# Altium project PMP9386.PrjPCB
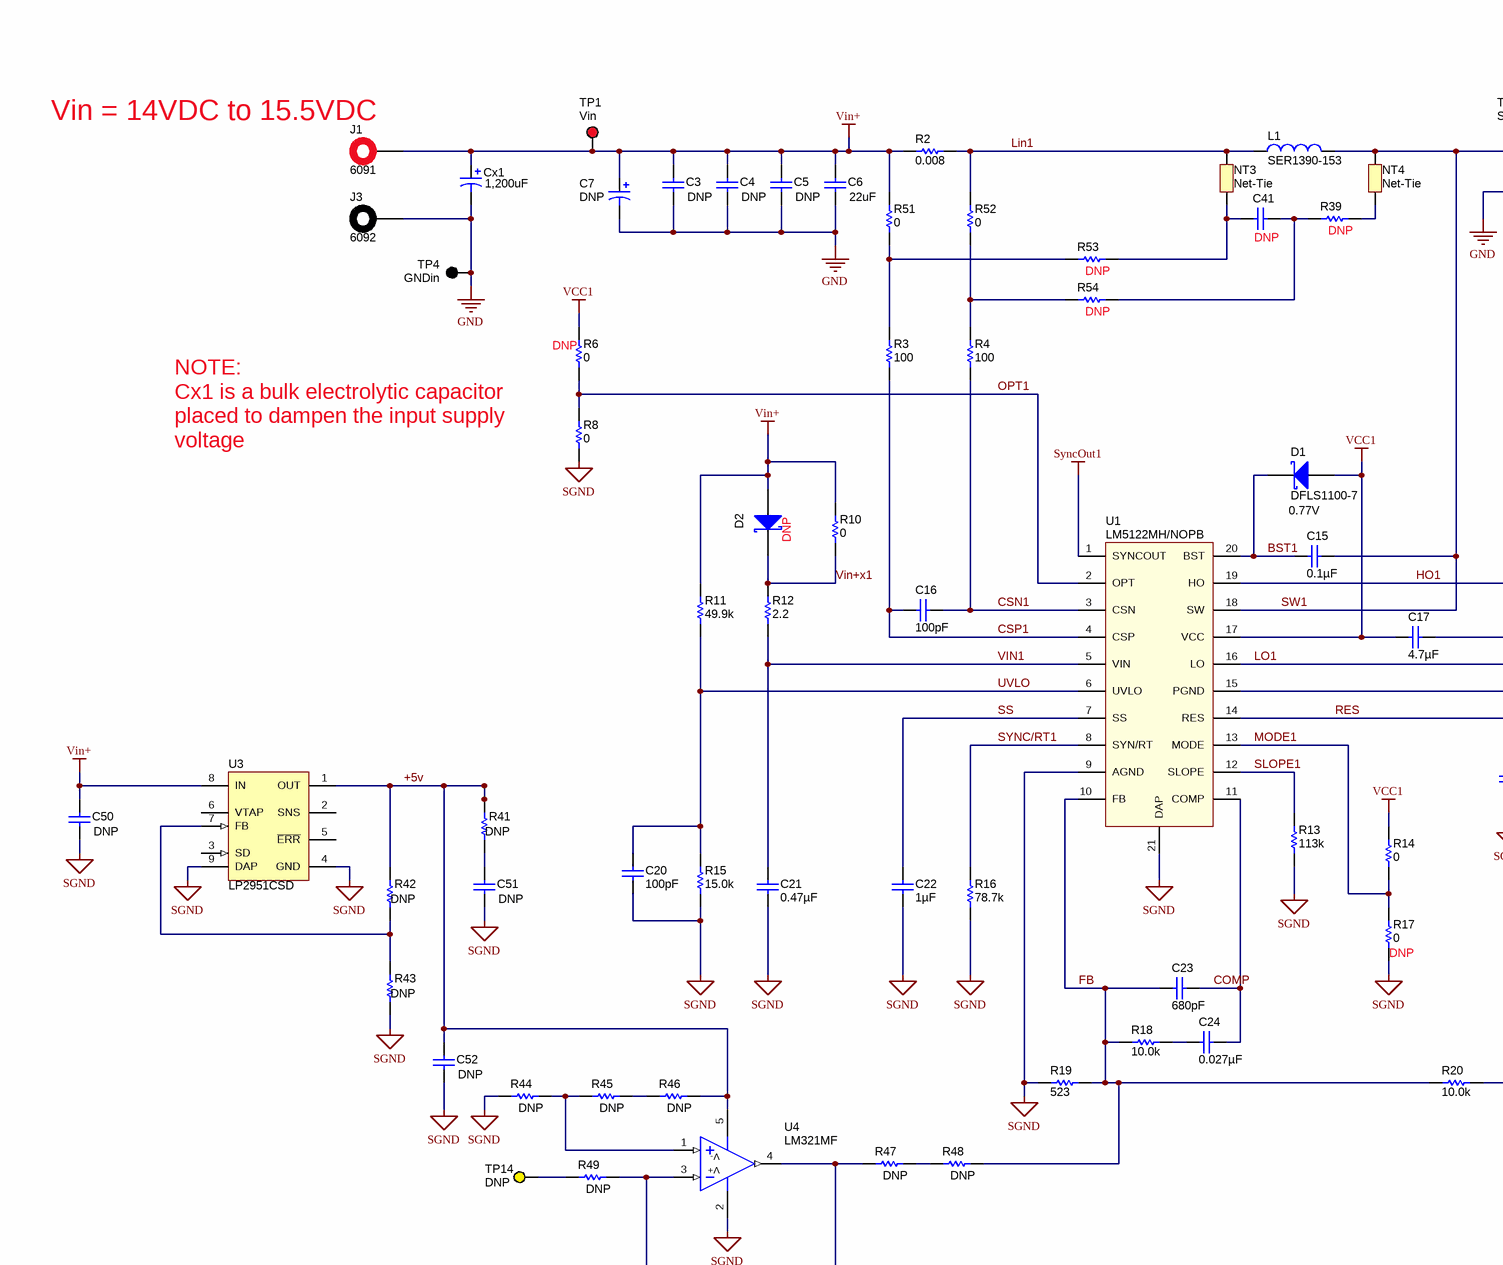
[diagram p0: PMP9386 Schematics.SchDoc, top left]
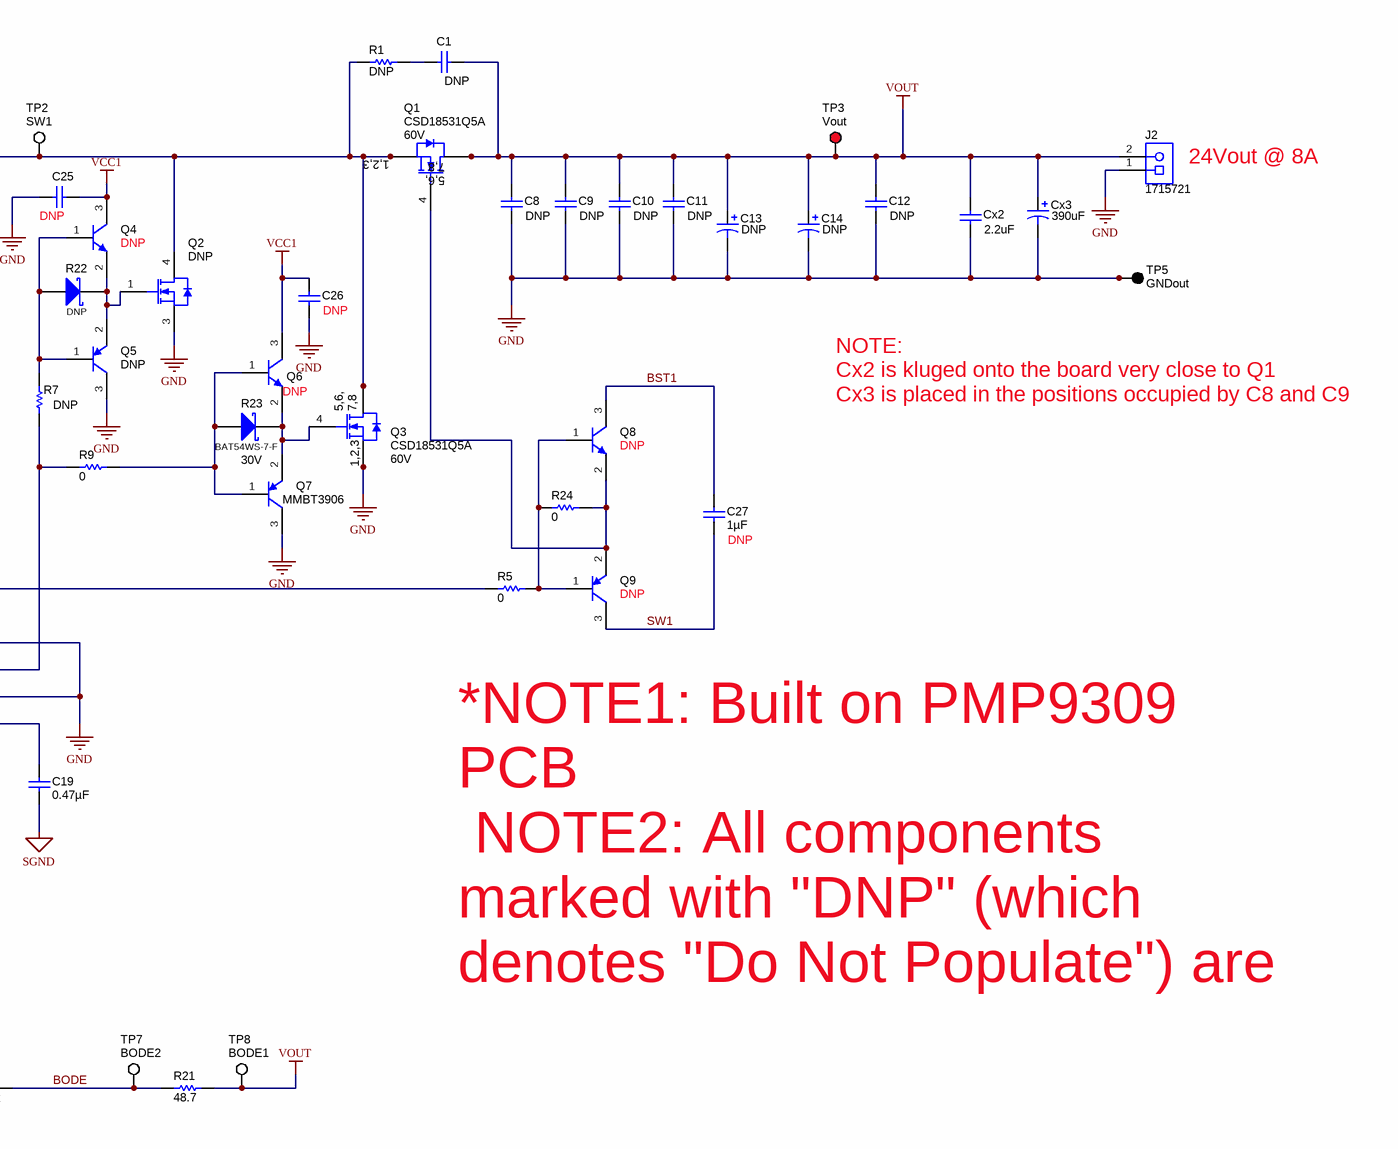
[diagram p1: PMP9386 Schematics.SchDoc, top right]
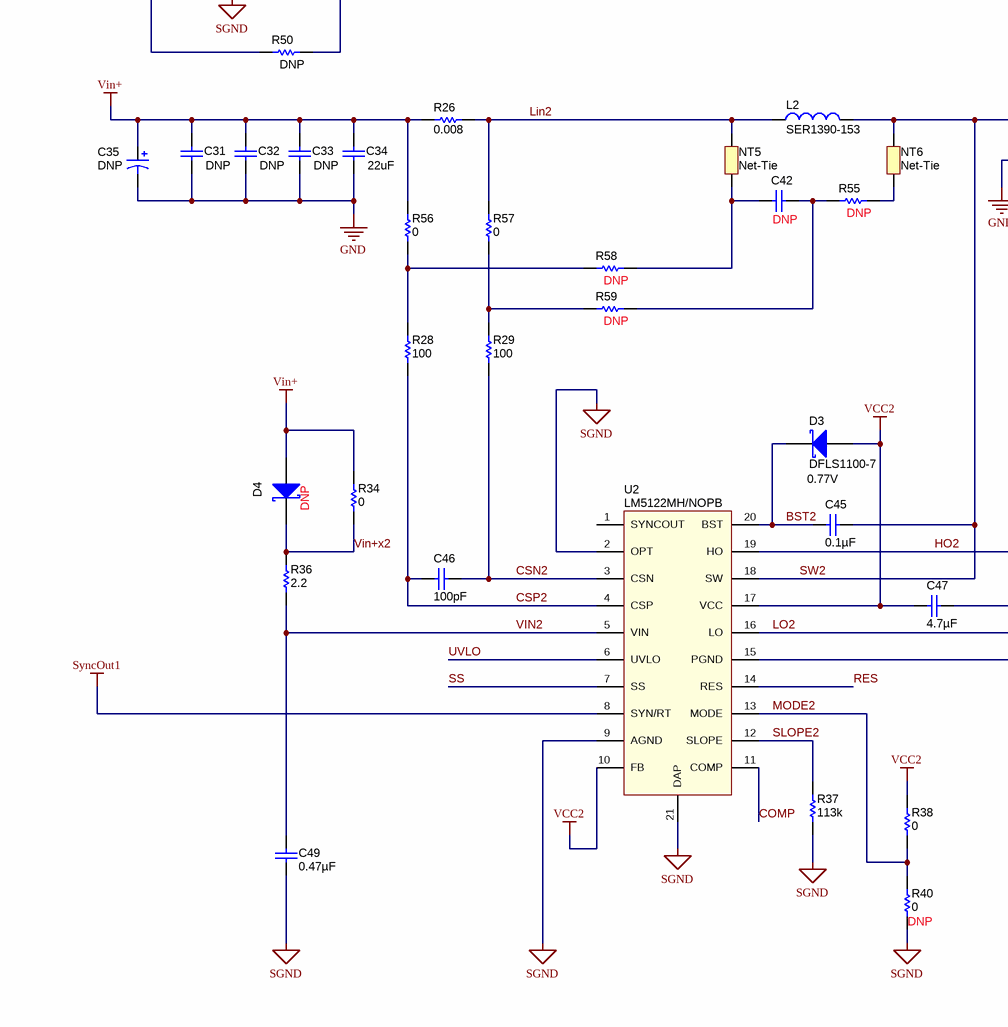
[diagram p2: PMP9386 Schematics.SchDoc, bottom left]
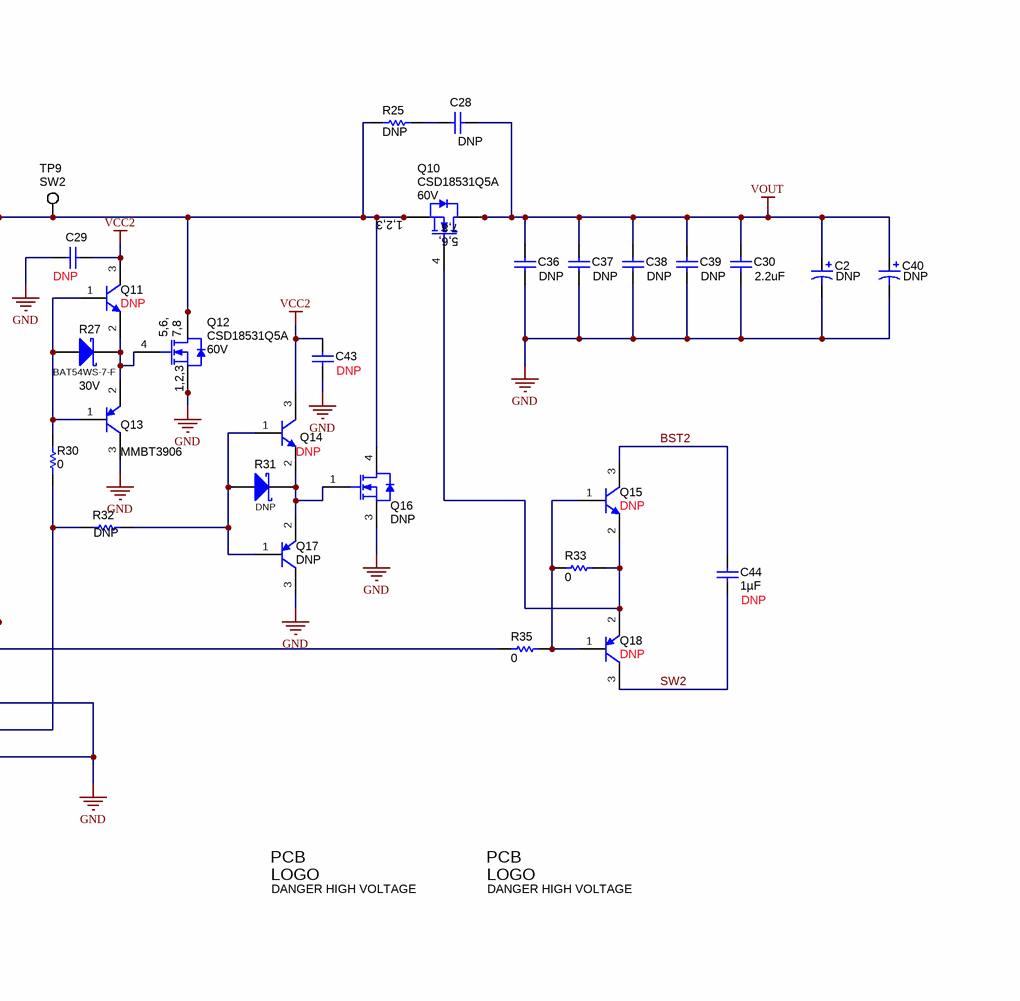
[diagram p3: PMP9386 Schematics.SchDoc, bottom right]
CopyrightYear: 2014; PCB_Layout: David Baba; PCB_Rev: Rev3C; PRJ_Customer: Public Release; PRJ_Engineer: David Baba; PRJ_Number: PMP9386; PRJ_Title: LM5122 Sync Boost; SCH_Rev: E1; TechSupport: http://www.ti.com/support; TID: PMP9386
2 sheets, 176 parts. Net scope: global (net labels, ports and power ports of the same name join across sheets).
Board file: PMP9309.PcbDoc
Sheets:
  PMP9386 Schematics.SchDoc
  PMP9386_Hardware_ANSI-B.SchDoc

## Sheet PMP9386 Schematics.SchDoc
size 558 x 431 mm; Date: Not shown in title block; ApprovedBy: Not shown in title block; CheckedBy: Not shown in title block; Author: Not shown in title block; CompanyName: Not shown in title block; Engineer: Not shown in title block; Organization: Not shown in title block; Address1: Not shown in title block; Address2: Not shown in title block; Address3: Not shown in title block; Address4: Not shown in title block; DocumentNumber: 1; Revision: Use project parameter SCH_Rev; SheetNumber: 1; SheetTotal: 2; PageSetup: Record=PageOptions¦CenterHorizontal=True¦CenterVertical=True¦PrintScale=0.62¦XCorrection=1.00¦YCorrection=1.00¦PrintKind=0¦BorderSize=5000000¦LeftOffset=0¦BottomOffset=0¦Orientation=2¦PaperLength=1000¦PaperWidth=1000¦Scale=100¦PaperSource=15¦PrintQuality=600¦MediaType=1¦DitherType=10¦PaperKind=11x17¦PrintScaleMode=1

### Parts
C1  DNP  [0805_HV]
C2  DNP  [SM_RADIAL_K16]
C3  DNP  [1210]
C4  DNP  [1210]
C5  DNP  [1210]
C6  22uF  [TBD]
C7  DNP  [TBD]
C8  DNP  [1210]
C9  DNP  [1210]
C10  DNP  [1210]
C11  DNP  [1210]
C12  DNP  [1210]
C13  DNP  [SM_RADIAL_K16]
C14  DNP  [SM_RADIAL_K16]
C15  ValueDisplayed: 0.1µF  [0603_HV]  (hidden comment: GRM188R72A104KA35D)
C16  ValueDisplayed: 100pF  [0603_HV]  (hidden comment: C1608C0G2A101J)
C17  ValueDisplayed: 4.7µF  [0805]  (hidden comment: GRM21BR71C475KA73L)
C19  ValueDisplayed: 0.47µF  [0603]  (hidden comment: GRM188R71E474KA12D)
C20  ValueDisplayed: 100pF  [0603_HV]  (hidden comment: GRM1885C1H101JA01D)
C21  ValueDisplayed: 0.47µF  [0603_HV]  (hidden comment: GRM188R71E474KA12D)
C22  ValueDisplayed: 1µF  [0805_HV]  (hidden comment: GRM219R71E105KA88D)
C23  ValueDisplayed: 680pF  [0603]  (hidden comment: C0603C681K5RACTU)
C24  ValueDisplayed: 0.027µF  [0805_HV]  (hidden comment: C0805C273K5RACTU)
C25  DNP  [0603]
C26  DNP  [0603]
C27  DNP  ValueDisplayed: 1µF  [0603]
C28  DNP  [0805_HV]
C29  DNP  [0603]
C30  2.2uF  [TBD]
C31  DNP  [1210]
C32  DNP  [1210]
C33  DNP  [1210]
C34  22uF  [TBD]
C35  DNP  [TBD]
C36  DNP  [1210]
C37  DNP  [1210]
C38  DNP  [1210]
C39  DNP  [1210]
C40  DNP  [SM_RADIAL_K16]
C41  DNP  [1206]
C42  DNP  [1206]
C43  DNP  [0603]
C44  DNP  ValueDisplayed: 1µF  [0603]
C45  ValueDisplayed: 0.1µF  [0603_HV]  (hidden comment: GRM188R72A104KA35D)
C46  ValueDisplayed: 100pF  [0603_HV]  (hidden comment: C1608C0G2A101J)
C47  ValueDisplayed: 4.7µF  [0805]  (hidden comment: GRM21BR71C475KA73L)
C49  ValueDisplayed: 0.47µF  [0603_HV]  (hidden comment: GRM188R71E474KA12D)
C50  DNP  [0603]
C51  DNP  [0603]
C52  DNP  [0603]
Cx1  1,200uF  [TBD]
Cx2  2.2uF  [TBD]
Cx3  390uF  [TBD]
D1  DFLS1100-7  value 0.77V  [powerDI123]
D2  DNP  [SOD-123F]
D3  DFLS1100-7  value 0.77V  [powerDI123]
D4  DNP  [SOD-123F]
J1  6091  [6091]
J2  1715721  [PhoenixContact_1715721]
J3  6092  [6092]
L1  SER1390-153
L2  SER1390-153
Logo2  DANGER HIGH VOLTAGE  [IEC_HighVoltage_Medium]  (no BOM)
Logo3  DANGER HIGH VOLTAGE  [IEC_HighVoltage_Medium]  (no BOM)
NT3  Net-Tie  [Net-Tie_10milWide_30milLong]  (net tie, no BOM)
NT4  Net-Tie  [Net-Tie_10milWide_30milLong]  (net tie, no BOM)
NT5  Net-Tie  [Net-Tie_10milWide_30milLong]  (net tie, no BOM)
NT6  Net-Tie  [Net-Tie_10milWide_30milLong]  (net tie, no BOM)
Q1  CSD18531Q5A  value 60V  [TRANS_NexFET_Q5A]
Q2  DNP  [DDPAK]
Q3  CSD18531Q5A  value 60V  [TRANS_NexFET_Q5A]
Q4  DNP  [SOT-23]
Q5  DNP  [SOT-23]
Q6  DNP  [SOT-23]
Q7  MMBT3906  [SOT-23]
Q8  DNP  [SOT-23]
Q9  DNP  [SOT-23]
Q10  CSD18531Q5A  value 60V  [TRANS_NexFET_Q5A]
Q11  DNP  [SOT-23]
Q12  CSD18531Q5A  value 60V  [TRANS_NexFET_Q5A]
Q13  MMBT3906  [SOT-23]
Q14  DNP  [SOT-23]
Q15  DNP  [SOT-23]
Q16  DNP  [DDPAK]
Q17  DNP  [SOT-23]
Q18  DNP  [SOT-23]
R1  DNP  [2010]
R2  value 0.008  [2512M]  (hidden comment: PMR100HZPFU8L00)
R3  value 100  [0603_HV]  (hidden comment: CRCW0603100RFKEA)
R4  value 100  [0603_HV]  (hidden comment: CRCW0603100RFKEA)
R5  value 0  [0603_HV]  (hidden comment: ERJ-3GEY0R00V)
R6  DNP  value 0  [0603_HV]
R7  DNP  [0603_HV]
R8  value 0  [0603_HV]  (hidden comment: ERJ-3GEY0R00V)
R9  value 0  [0603_HV]  (hidden comment: ERJ-3GEY0R00V)
R10  value 0  [0603]  (hidden comment: ERJ-3GEY0R00V)
R11  value 49.9k  [0603]  (hidden comment: CRCW060349K9FKEA)
R12  value 2.2  [0805_HV]  (hidden comment: CRCW08052R20JNEA)
R13  value 113k  [0603]  (hidden comment: CRCW0603113KFKEA)
R14  value 0  [0603]  (hidden comment: ERJ-3GEY0R00V)
R15  value 15.0k  [0603]  (hidden comment: CRCW060315K0FKEA)
R16  value 78.7k  [0603]  (hidden comment: CRCW060378K7FKEA)
R17  DNP  value 0  [0603]
R18  value 10.0k  [0603]  (hidden comment: CRCW060310K0FKEA)
R19  value 523  [0603]  (hidden comment: CRCW0603523RFKEA)
R20  value 10.0k  [0603]  (hidden comment: CRCW060310K0FKEA)
R21  value 48.7  [0805_HV]  (hidden comment: CRCW080548R7FKEA)
R22  DNP  [sod-323]
R23  BAT54WS-7-F  value 30V  [sod-323]
R24  value 0  [0603]  (hidden comment: CRCW06030000Z0EA)
R25  DNP  [2010]
R26  value 0.008  [2512M]  (hidden comment: PMR100HZPFU8L00)
R27  BAT54WS-7-F  value 30V  [sod-323]
R28  value 100  [0603_HV]  (hidden comment: CRCW0603100RFKEA)
R29  value 100  [0603_HV]  (hidden comment: CRCW0603100RFKEA)
R30  value 0  [0603_HV]  (hidden comment: ERJ-3GEY0R00V)
R31  DNP  [sod-323]
R32  DNP  [0603_HV]
R33  value 0  [0603]  (hidden comment: CRCW06030000Z0EA)
R34  value 0  [0603]  (hidden comment: ERJ-3GEY0R00V)
R35  value 0  [0603_HV]  (hidden comment: ERJ-3GEY0R00V)
R36  value 2.2  [0805_HV]  (hidden comment: CRCW08052R20JNEA)
R37  value 113k  [0603]  (hidden comment: CRCW0603113KFKEA)
R38  value 0  [0603]  (hidden comment: ERJ-3GEY0R00V)
R39  DNP  [0805_HV]
R40  DNP  value 0  [0603]
R41  DNP  [0603]
R42  DNP  [0603]
R43  DNP  [0603]
R44  DNP  [0603]
R45  DNP  [0603]
R46  DNP  [0603]
R47  DNP  [0603]
R48  DNP  [0603]
R49  DNP  [0603]
R50  DNP  [0603]
R51  value 0  [0603]  (hidden comment: CRCW06030000Z0EA)
R52  value 0  [0603]  (hidden comment: CRCW06030000Z0EA)
R53  DNP  [1206]
R54  DNP  [1206]
R55  DNP  [0805_HV]
R56  value 0  [0603]  (hidden comment: CRCW06030000Z0EA)
R57  value 0  [0603]  (hidden comment: CRCW06030000Z0EA)
R58  DNP  [1206]
R59  DNP  [1206]
TP1  Vin  [Keystone5010]
TP2  SW1  [Keystone5012]
TP3  Vout  [Keystone5010]
TP4  GNDin  [Keystone5011]
TP5  GNDout  [Keystone5011]
TP7  BODE2  [Keystone5012]
TP8  BODE1  [Keystone5012]
TP9  SW2  [Keystone5012]
TP14  DNP  [Keystone5009]
U1  LM5122MH/NOPB  [PWP0020A_N]
U2  LM5122MH/NOPB  [PWP0020A_N]
U3  LP2951CSD  [SDC08A]
U4  LM321MF  [MF05A_L]

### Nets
GND: C2.2(-) C3.2 C4.2 C5.2 C6.2 C7.2(-) C8.2 C9.2 C10.2 C11.2 C12.2 C13.2(-) C14.2(-) C17.1 C25.2 C26.2 C29.2 C30.2 C31.2 C32.2 C33.2 C34.2 C35.2(-) C36.2 C37.2 C38.2 C39.2 C40.2(-) C43.2 C47.1 Cx1.2(-) Cx2.2 Cx3.2(-) J2.1 J3.1 Q2.3(S) Q3.1(S) Q3.2(S) Q3.3(S) Q5.3(C) Q7.3(C) Q12.1(S) Q12.2(S) Q12.3(S) Q13.3(C) Q16.3(S) Q17.3(C) TP4.1 TP5.1 U1.15(PGND) U2.15(PGND)
SGND: C19.2 C20.2 C21.2 C22.2 C49.2 C50.2 C51.2 C52.2 R8.1 R13.1 R15.1 R16.1 R17.1 R19.2 R37.1 R40.1 R43.1 R44.1 U1.9(AGND) U1.21(DAP) U2.2(OPT) U2.9(AGND) U2.21(DAP) U3.4(GND) U3.9(DAP) U4.2(V-)
SyncOut1: U1.1(SYNCOUT) U2.8(SYN/RT)
VCC1: C17.2 C25.1 C26.1 D1.2(A) Q4.3(C) Q6.3(C) R6.2 R14.2 U1.17(VCC)
VCC2: C29.1 C43.1 C47.2 D3.2(A) Q11.3(C) Q14.3(C) R38.2 U2.10(FB) U2.17(VCC)
Vin+: C3.1 C4.1 C5.1 C6.1 C7.1(+) C31.1 C32.1 C33.1 C34.1 C35.1(+) C50.1 Cx1.1(+) D2.2(A) D4.2(A) J1.1 R2.2 R10.2 R11.2 R26.2 R34.2 R51.2 R56.2 TP1.1 U3.8(IN)
VOUT: C1.2 C2.1(+) C8.1 C9.1 C10.1 C11.1 C12.1 C13.1(+) C14.1(+) C28.2 C30.1 C36.1 C37.1 C38.1 C39.1 C40.1(+) Cx2.1 Cx3.1(+) J2.2 Q1.5(D) Q1.6(D) Q1.7(D) Q1.8(D) Q1.9(D) Q10.5(D) Q10.6(D) Q10.7(D) Q10.8(D) Q10.9(D) R21.1 TP3.1 TP8.1
+5v: C52.1 R41.2 R42.2 R46.2 U3.1(OUT) U4.5(V+)
BODE: R20.2 R21.2 TP7.1
BST1: C15.2 C27.1 D1.1(K) Q8.3(C) U1.20(BST)
BST2: C44.1 C45.2 D3.1(K) Q15.3(C) U2.20(BST)
COMP: C23.2 C24.2 U1.11(COMP) U2.11(COMP)
CSN1: C16.1 R4.1 U1.3(CSN)
CSN2: C46.1 R29.1 U2.3(CSN)
CSP1: C16.2 R3.1 U1.4(CSP)
CSP2: C46.2 R28.1 U2.4(CSP)
FB: C23.1 R18.1 R19.1 R20.1 R48.2 U1.10(FB)
HO1: R5.2 U1.19(HO)
HO2: R35.2 U2.19(HO)
Lin1: L1.1 NT3.2 R2.1 R52.2
Lin2: L2.1 NT5.2 R26.1 R57.2
LO1: R7.1 R9.2 U1.16(LO)
LO2: R30.1 R32.2 U2.16(LO)
MODE1: R14.1 R17.2 U1.13(MODE)
MODE2: R38.1 R40.2 U2.13(MODE)
OPT1: R6.1 R8.2 U1.2(OPT)
RES: C19.1 U1.14(RES) U2.14(RES)
SLOPE1: R13.2 U1.12(SLOPE)
SLOPE2: R37.2 U2.12(SLOPE)
SS: C22.1 U1.7(SS) U2.7(SS)
SW1: C15.1 C27.2 L1.2 NT4.2 Q1.1(S) Q1.2(S) Q1.3(S) Q2.4(D) Q3.5(D) Q3.6(D) Q3.7(D) Q3.8(D) Q3.9(D) Q9.3(C) R1.2 TP2.1 U1.18(SW)
SW2: C44.2 C45.1 L2.2 NT6.2 Q10.1(S) Q10.2(S) Q10.3(S) Q12.5(D) Q12.6(D) Q12.7(D) Q12.8(D) Q12.9(D) Q16.4(D) Q18.3(C) R25.2 TP9.1 U2.18(SW)
SYNC/RT1: R16.2 U1.8(SYN/RT)
UVLO: C20.1 R11.1 R15.2 U1.6(UVLO) U2.6(UVLO)
VIN1: C21.1 R12.1 U1.5(VIN)
VIN2: C49.1 R36.1 U2.5(VIN)
Vin+x1: D2.1(K) R10.1 R12.2
Vin+x2: D4.1(K) R34.1 R36.2
NetC1_1: C1.1 R1.1
NetC24_1: C24.1 R18.2
NetC28_1: C28.1 R25.1
NetC41_1: C41.1 R39.1 R54.2
NetC41_2: C41.2 NT3.1 R53.2
NetC42_1: C42.1 R55.1 R59.2
NetC42_2: C42.2 NT5.1 R58.2
NetC51_1: C51.1 R41.1
NetNT4_1: NT4.1 R39.2
NetNT6_1: NT6.1 R55.2
NetQ1_4: Q1.4(G) Q8.2(E) Q9.2(E) R24.2
NetQ2_1: Q2.1(G) Q4.2(E) Q5.2(E) R22.1(K)
NetQ3_4: Q3.4(G) Q6.2(E) Q7.2(E) R23.1(K)
NetQ4_1: Q4.1(B) Q5.1(B) R7.2 R22.2(A)
NetQ6_1: Q6.1(B) Q7.1(B) R9.1 R23.2(A)
NetQ8_1: Q8.1(B) Q9.1(B) R5.1 R24.1
NetQ10_4: Q10.4(G) Q15.2(E) Q18.2(E) R33.2
NetQ11_1: Q11.1(B) Q13.1(B) R27.2(A) R30.2
NetQ11_2: Q11.2(E) Q12.4(G) Q13.2(E) R27.1(K)
NetQ14_1: Q14.1(B) Q17.1(B) R31.2(A) R32.1
NetQ14_2: Q14.2(E) Q16.1(G) Q17.2(E) R31.1(K)
NetQ15_1: Q15.1(B) Q18.1(B) R33.1 R35.1
NetR3_2: R3.2 R51.1 R53.1
NetR4_2: R4.2 R52.1 R54.1
NetR28_2: R28.2 R56.1 R58.1
NetR29_2: R29.2 R57.1 R59.1
NetR42_1: R42.1 R43.2 U3.7(FB)
NetR44_2: R44.2 R45.1 U4.1(IN+)
NetR45_2: R45.2 R46.1
NetR47_1: R47.1 R50.2 U4.4(OUT)
NetR47_2: R47.2 R48.1
NetR49_1: R49.1 TP14.1
NetR49_2: R49.2 R50.1 U4.3(IN-)

Not connected (* = marked no-connect by the designer): U2 1(SYNCOUT); U3 2(SNS) 3(SD) 5(~{ERR}) 6(VTAP)

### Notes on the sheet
- (near J1) Vin = 14VDC to 15.5VDC
- (near J2) 24Vout @ 8A
- NOTE:
  Cx2 is kluged onto the board very close to Q1
  Cx3 is placed in the positions occupied by C8 and C9
- NOTE:
  Cx1 is a bulk electrolytic capacitor placed to dampen the input supply voltage
- *NOTE1: Built on PMP9309 PCB
  NOTE2: All components marked with "DNP" (which denotes "Do Not Populate") are components that should NOT be installed in the circuit.

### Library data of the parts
C1 C28 = GRM2165C2A471JA01D: CAP, CERM, 470pF, 100V, +/-5%, C0G/NP0, 0805; Manufacturer: MuRata; Polarized: N; CompType: Capacitor; U/M: EA; Cap_F: 0.00000000047; Tolerance_%: 5; VDC_V: 100; TaMin_C: -55; TaMax_C: 125; Cap_Case: 0805
C2 C13 C14 C40 = EEV-FK2A331M: CAP, AL, 330uF, 100V, +/-20%, 0.153 ohm, SMD; Manufacturer: Panasonic; Polarized: Y; CompType: Capacitor; U/M: EA; ValueDisplayed: 330µF; Cap_F: 0.00033; Tolerance_%: 20; VDC_V: 100; ESR_Ohm: 0.153; IRMS_A: 0.917; TaMin_C: -55; TaMax_C: 105; Cap_Case: K16
C3-C5 C31-C33 = GRM32DR71H335KA88L: CAP, CERM, 3.3uF, 50V, +/-10%, X7R, 1210; Manufacturer: MuRata; CompType: Capacitor; U/M: EA; Tolerance_%: 10; VDC_V: 50; TaMin_C: -55; TaMax_C: 125; Polarized: N; ValueDisplayed: 3.3µF; Cap_F: 0.0000033; ESR_Ohm: 0.003; Value1: 0.003 ohm
C6 C34 = Capacitor: CAP, CERM, 22uF, 25V, X7R, 20%, 1210; Manufacturer: Taiyo Yuden; PartNumber: TMK325B7226MM; Polarized: N; U/M: EA
C7 C35 = Capacitor_Polarized: CAP, Al Electrolytic, 330uF, 35V, SMT; Manufacturer: SUNCON; PartNumber: 35CE330KX; Polarized: Y; U/M: EA
C8-C11 C36-C39 = GRM32CR72A105KA35L: CAP, CERM, 1uF, 100V, +/-10%, X7R, 1210; Manufacturer: MuRata; CompType: Capacitor; U/M: EA; Tolerance_%: 10; VDC_V: 100; Polarized: N; ValueDisplayed: 1µF; Cap_F: 0.000001; Value1: Unknown; TaMin_C: -55; TaMax_C: 125
C12 = GRM32CR72A105KA35L: CAP, CERM, 1uF, 100V, +/-10%, X7R, 1210; Manufacturer: MuRata; Polarized: N; CompType: Capacitor; ValueDisplayed: 1µF; U/M: EA; Cap_F: 0.000001; Tolerance_%: 10; Value1: Unknown; VDC_V: 100; TaMin_C: -55; TaMax_C: 125
C15 C45 = GRM188R72A104KA35D: CAP, CERM, 0.1uF, 100V, +/-10%, X7R, 0603; Manufacturer: MuRata; Polarized: N; CompType: Capacitor; U/M: EA; Cap_F: 0.0000001; Tolerance_%: 10; Value1: Unknown; VDC_V: 100; TaMin_C: -55; TaMax_C: 125; Cap_Case: 0603
C16 C46 = C1608C0G2A101J: CAP, CERM, 100pF, 100V, +/-5%, C0G/NP0, 0603; Manufacturer: TDK; Polarized: N; CompType: Capacitor; U/M: EA; Cap_F: 0.0000000001; Tolerance_%: 5; ESR_Ohm: 0.1202; Value1: 0.1202 ohm; VDC_V: 100; TaMin_C: -55; TaMax_C: 125; Cap_Case: 0603
C17 C47 = GRM21BR71C475KA73L: CAP, CERM, 4.7uF, 16V, +/-10%, X7R, 0805; Manufacturer: MuRata; Polarized: N; CompType: Capacitor; U/M: EA; Cap_F: 0.0000047; Tolerance_%: 10; ESR_Ohm: 0.006; Value1: 0.006 ohm; VDC_V: 16; TaMin_C: -55; TaMax_C: 125
C19 = GRM188R71E474KA12D: CAP, CERM, 0.47uF, 25V, +/-10%, X7R, 0603; Manufacturer: MuRata; Polarized: N; CompType: Capacitor; U/M: EA; Cap_F: 0.00000047; Tolerance_%: 10; VDC_V: 25; TaMin_C: -55; TaMax_C: 125
C20 = GRM1885C1H101JA01D: CAP, CERM, 100pF, 50V, +/-5%, C0G/NP0, 0603; Manufacturer: MuRata; Polarized: N; CompType: Capacitor; U/M: EA; Cap_F: 0.0000000001; Tolerance_%: 5; VDC_V: 50; TaMin_C: -55; TaMax_C: 125; Cap_Case: 0603
C21 C49 = GRM188R71E474KA12D: CAP, CERM, 0.47uF, 25V, +/-10%, X7R, 0603; Manufacturer: MuRata; Polarized: N; CompType: Capacitor; U/M: EA; Cap_F: 0.00000047; Tolerance_%: 10; VDC_V: 25; TaMin_C: -55; TaMax_C: 125; Cap_Case: 0603
C22 = GRM219R71E105KA88D: CAP, CERM, 1uF, 25V, +/-10%, X7R, 0805; Manufacturer: MuRata; Polarized: N; CompType: Capacitor; U/M: EA; Cap_F: 0.000001; Tolerance_%: 10; Value1: Unknown; VDC_V: 25; TaMin_C: -55; TaMax_C: 125; Cap_Case: 0805
C23 = C0603C681K5RACTU: CAP, CERM, 680pF, 50V, +/-10%, X7R, 0603; Manufacturer: Kemet; Polarized: N; CompType: Capacitor; U/M: EA; Cap_F: 0.00000000068; Tolerance_%: 10; Value1: Unknown; VDC_V: 50; TaMin_C: -55; TaMax_C: 125
C24 = C0805C273K5RACTU: CAP, CERM, 0.027uF, 50V, +/-10%, X7R, 0805; Manufacturer: Kemet; Polarized: N; CompType: Capacitor; U/M: EA; Cap_F: 0.000000027; Tolerance_%: 10; ESR_Ohm: 0.115; Value1: 0.115 ohm; VDC_V: 50; IRMS_A: 0.728; TaMin_C: -55; TaMax_C: 125; Cap_Case: 0805
C25 C26 C29 C43 = GRM188R71E105KA12D: CAP, CERM, 1uF, 25V, +/-10%, X7R, 0603; Manufacturer: MuRata; Polarized: N; CompType: Capacitor; ValueDisplayed: 1µF; U/M: EA; Cap_F: 0.000001; Tolerance_%: 10; Value1: Unknown; VDC_V: 25; TaMin_C: -55; TaMax_C: 125
C27 C44 = GRM188R71E105KA12D: CAP, CERM, 1uF, 25V, +/-10%, X7R, 0603; Manufacturer: MuRata; Polarized: N; CompType: Capacitor; U/M: EA; Cap_F: 0.000001; Tolerance_%: 10; Value1: Unknown; VDC_V: 25; TaMin_C: -55; TaMax_C: 125
C30 Cx2 = Capacitor: CAP, CERM, 2.2uF, 25V, X7R, 0805; Manufacturer: AVX; PartNumber: 08053C225MAT; Polarized: N; U/M: EA
C41 C42 = GRM31CR71H225KA88L: CAP, CERM, 2.2uF, 50V, +/-10%, X7R, 1206; Manufacturer: MuRata; Polarized: N; CompType: Capacitor; ValueDisplayed: 2.2µF; U/M: EA; Cap_F: 0.0000022; Tolerance_%: 10; Value1: Unknown; VDC_V: 50; TaMin_C: -55; TaMax_C: 125
C50 = 06035C104KAT2A: CAP, CERM, 0.1uF, 50V, +/-10%, X7R, 0603; Manufacturer: AVX; Polarized: N; CompType: Capacitor; ValueDisplayed: 0.1µF; U/M: EA; Cap_F: 0.0000001; Tolerance_%: 10; Value1: Unknown; VDC_V: 50; TaMin_C: -55; TaMax_C: 125
C51 = GRM188R71A225KE15D: CAP, CERM, 2.2uF, 10V, +/-10%, X7R, 0603; Manufacturer: MuRata; Polarized: N; CompType: Capacitor; ValueDisplayed: 2.2µF; U/M: EA; Cap_F: 0.0000022; Tolerance_%: 10; ESR_Ohm: 0.009; Value1: 0.009 ohm; TaMin_C: -55; TaMax_C: 125
C52 = C0603C474K4RACTU: CAP, CERM, 0.47uF, 16V, +/-10%, X7R, 0603; Manufacturer: Kemet; Polarized: N; CompType: Capacitor; ValueDisplayed: 0.47µF; U/M: EA; Cap_F: 0.00000047; Tolerance_%: 10; Value1: Unknown; VDC_V: 16; TaMin_C: -55; TaMax_C: 125
Cx1 = Capacitor_Polarized: CAP, Electrolytic, 1,200uF, 25V, TH; Manufacturer: Suncon; PartNumber: 16ME1200AX; Polarized: Y; U/M: EA
Cx3 = Capacitor_Polarized: CAP, Conductive Polymer Al Electrolytic, 390F, 25V, 4.2Arms, +/-20%, 0.021Ohm ESR, SMT; Manufacturer: Nichicon; PartNumber: PCV1E391MCL2GS; Polarized: Y; U/M: EA
D1 D3 = DFLS1100-7: Diode, Schottky, 100V, 1A, PowerDI123; Manufacturer: Diodes Inc.; U/M: EA; Vf_V: 0.77; Io_A: 1; Vr_V: 100; TJmax_C: 175; RJC_CperW: 7
D2 D4 = PMEG6010CEH,115: Diode, Schottky, 60V, 1A, SOD-123F; Manufacturer: NXP Semiconductor; Value: 0.57V; U/M: EA; Vf_V: 0.57; Io_A: 1; Vr_V: 60; TJmax_C: 150
J1 = 6091: Standard Banana Jack, Insulated, Red; Manufacturer: Keystone; SymbolCreator: a0412235; CompType: Connector; U/M: EA
J2 = 1715721: Conn Term Block, 2POS, 5.08mm, TH; Manufacturer: Phoenix Contact; Value: 2x1; CompType: Terminal Block; U/M: EA; SymbolCreator: a0412235
J3 = 6092: Standard Banana Jack, Insulated, Black; Manufacturer: Keystone; SymbolCreator: a0412235; CompType: Connector; U/M: EA
L1 L2 = Inductor: Inductor, 15uH, 7.2A @ 10% drop, 0.015ohm Max., SMT; Manufacturer: Coilcraft; U/M: EA
Logo2 Logo3 = IEC_HighVoltage: IEC 61010-1 High Voltage Warning; SymbolCreator: codlsc
NT3-NT6 = Net-Tie: Single point connection between nets.; SymbolCreator: codlsc
Q1 Q3 Q10 Q12 = CSD18531Q5A: MOSFET, N-CH, 60V, 19A, SON 5x6mm; Manufacturer: Texas Instruments; Alternate Manufacturer: None; U/M: EA; VdsMax_V: 60; IdsMax_A: 19; ChType: N; Value1: 0.0044 ohm; Value2: 18 nC; QgTyp_nC: 18; Vgs_V: 20; Rdson45_Ohm: 0.0044
Q2 Q16 = SUM40N15-38: MOSFET, N-CH, 150V, 40A, DDPAK; Manufacturer: Vishay-Siliconix; Alternate Manufacturer: None; U/M: EA; VdsMax_V: 150; IdsMax_A: 40; ChType: N; Value1: 1.25 ohm; Value2: 38 nC; QgTyp_nC: 38; Vgs_V: 20; Rdson45_Ohm: 1.25
Q4 Q6 Q8 Q11 Q14 Q15 = MMBT3904, Fairchild Semiconductor: Transistor, NPN, 40V, 0.2A, SOT-23; CompType: BJT; PNP: 0; NPN: 1; Vceo_V: 40; Vcesat1_V: 0.2; Value: 0.2V; HfeMax: 300; TaMin_C: -55; TaMax_C: 150; U/M: EA
Q5 Q7 Q9 Q13 Q17 Q18 = MMBT3906, Fairchild Semiconductor: Transistor, PNP, 40V, 0.2A, SOT-23; CompType: BJT; PNP: 1; NPN: 0; Vceo_V: 40; Vcesat1_V: 0.25; Value: 0.25V; IcRated_A: 0.2; HfeMax: 300; TaMin_C: -55; TaMax_C: 150; U/M: EA
R1 R25 = CRCW20108R20JNEF: RES 8.2 OHM 3/4W 5% 2010 SMD; Manufacturer: Vishay Dale; CompType: Used in some BOM reports.  Useful for finding later.; SymbolVersion: use current date i.e. 2008-05-20; Value: 8.2; Power_W: 0.75W, 3/4W; TempCo: ±200ppm/°C; U/M: EA, IN, or GM; SymbolCreator: Use LDAP id
R2 R26 = PMR100HZPFU8L00: RES, 0.008 ohm, 1%, 2W, 2512; Manufacturer: Rohm; CompType: Resistor; U/M: EA; Tolerance_%: 1; TempCo: 100 ppm/C; Power_W: 2; Value_Code: R008; EIA_Code: E96
R3 R4 R28 R29 = CRCW0603100RFKEA: RES, 100 ohm, 1%, 0.1W, 0603; Manufacturer: Vishay-Dale; Alternate PartNumber: Equivalent; Alternate Manufacturer: Any; CompType: Resistor; Value_Code: 100R; Tolerance_%: 1; Power_W: 0.1; VDC_V: 75; TempCo: 100 ppm/C; EIA_Code: E96; U/M: EA
R5 R6 R8-R10 R14 R17 R30 R34 R35 R38 R40 = ERJ-3GEY0R00V: RES, 0 ohm, 5%, 0.1W, 0603; Manufacturer: Panasonic; CompType: Resistor; Value_Code: 0000; Tolerance_%: 5; Power_W: 0.1; VDC_V: 50; TempCo: 600 ppm/C; EIA_Code: E24; U/M: EA
R7 R32 = ERJ-3GEY0R00V: RES, 0 ohm, 5%, 0.1W, 0603; Manufacturer: Panasonic; CompType: Resistor; Value: 0; Value_Code: 0000; Tolerance_%: 5; Power_W: 0.1; VDC_V: 50; TempCo: 600 ppm/C; EIA_Code: E24; U/M: EA
R11 = CRCW060349K9FKEA: RES, 49.9k ohm, 1%, 0.1W, 0603; Manufacturer: Vishay-Dale; CompType: Resistor; Res_ohm: 49900; Value_Code: 49k9; Tolerance_%: 1; Power_W: 0.1; VDC_V: 75; TempCo: 100 ppm/C; EIA_Code: E96; U/M: EA
R12 R36 = CRCW08052R20JNEA: RES, 2.2 ohm, 5%, 0.125W, 0805; Manufacturer: Vishay-Dale; CompType: Resistor; Value_Code: 2R20; Tolerance_%: 5; Power_W: 0.125; VDC_V: 150; TempCo: 200 ppm/C; EIA_Code: E24; U/M: EA
R13 R37 = CRCW0603113KFKEA: RES, 113k ohm, 1%, 0.1W, 0603; Manufacturer: Vishay-Dale; CompType: Resistor; Res_ohm: 113000; Tolerance_%: 1; Power_W: 0.1; VDC_V: 75; TempCo: 100 ppm/C; EIA_Code: E96; U/M: EA
R15 = CRCW060315K0FKEA: RES, 15.0k ohm, 1%, 0.1W, 0603; Manufacturer: Vishay-Dale; CompType: Resistor; Res_ohm: 15000; Value_Code: 15k0; Tolerance_%: 1; Power_W: 0.1; VDC_V: 75; TempCo: 100 ppm/C; EIA_Code: E96; U/M: EA
R16 = CRCW060378K7FKEA: RES, 78.7k ohm, 1%, 0.1W, 0603; Manufacturer: Vishay-Dale; CompType: Resistor; Res_ohm: 78700; Value_Code: 78k7; Tolerance_%: 1; Power_W: 0.1; VDC_V: 75; TempCo: 100 ppm/C; EIA_Code: E96; U/M: EA
R18 R20 R43 = CRCW060310K0FKEA: RES, 10.0k ohm, 1%, 0.1W, 0603; Manufacturer: Vishay-Dale; CompType: Resistor; Res_ohm: 10000; Value_Code: 10k0; Tolerance_%: 1; Power_W: 0.1; VDC_V: 75; TempCo: 100 ppm/C; EIA_Code: E96; U/M: EA
R19 = CRCW0603523RFKEA: RES, 523 ohm, 1%, 0.1W, 0603; Manufacturer: Vishay-Dale; CompType: Resistor; Value_Code: 523R; Tolerance_%: 1; Power_W: 0.1; VDC_V: 75; TempCo: 100 ppm/C; EIA_Code: E96; U/M: EA
R21 = CRCW080548R7FKEA: RES, 48.7 ohm, 1%, 0.125W, 0805; Manufacturer: Vishay-Dale; CompType: Resistor; Value_Code: 48R7; Tolerance_%: 1; Power_W: 0.125; VDC_V: 150; TempCo: 100 ppm/C; EIA_Code: E96; U/M: EA
R22 R23 R27 R31 = BAT54WS-7-F: Diode, Schottky, 30V, 0.2A, SOD-323; Manufacturer: Diodes Inc.; Value2: 0.7V; U/M: EA; Vf_V: 0.7; Io_A: 0.2; Vr_V: 30; TJmax_C: 125
R24 R33 R51 R52 R56 R57 = CRCW06030000Z0EA: RES, 0 ohm, 5%, 0.1W, 0603; Manufacturer: Vishay-Dale; CompType: Resistor; Value_Code: 0000; Tolerance_%: 5; Power_W: 0.1; VDC_V: 75; TempCo: 200 ppm/C; EIA_Code: E24; U/M: EA
R39 R55 = CRCW0805825RFKEA: RES, 825 ohm, 1%, 0.125W, 0805; Manufacturer: Vishay-Dale; CompType: Resistor; Value: 825; Value_Code: 825R; Tolerance_%: 1; Power_W: 0.125; VDC_V: 150; TempCo: 100 ppm/C; EIA_Code: E96; U/M: EA
R41 R48 = CRCW06030000Z0EA: RES, 0 ohm, 5%, 0.1W, 0603; Manufacturer: Vishay-Dale; CompType: Resistor; Value: 0; Value_Code: 0000; Tolerance_%: 5; Power_W: 0.1; VDC_V: 75; TempCo: 200 ppm/C; EIA_Code: E24; U/M: EA
R42 = CRCW060388K7FKEA: RES, 88.7k ohm, 1%, 0.1W, 0603; Manufacturer: Vishay-Dale; CompType: Resistor; Res_ohm: 88700; Value_Code: 88k7; Tolerance_%: 1; Power_W: 0.1; VDC_V: 75; TempCo: 100 ppm/C; EIA_Code: E96; U/M: EA
R44 R49 = CRCW06031K00FKEA: RES, 1.00k ohm, 1%, 0.1W, 0603; Manufacturer: Vishay-Dale; CompType: Resistor; Res_ohm: 1000; Value_Code: 1k00; Tolerance_%: 1; Power_W: 0.1; VDC_V: 75; TempCo: 100 ppm/C; EIA_Code: E96; U/M: EA
R45 = CRCW06033K74FKEA: RES, 3.74k ohm, 1%, 0.1W, 0603; Manufacturer: Vishay-Dale; CompType: Resistor; Res_ohm: 3740; Value_Code: 3k74; Tolerance_%: 1; Power_W: 0.1; VDC_V: 75; TempCo: 100 ppm/C; EIA_Code: E96; U/M: EA
R46 = CRCW060340R2FKEA: RES, 40.2 ohm, 1%, 0.1W, 0603; Manufacturer: Vishay-Dale; CompType: Resistor; Value: 40.2; Value_Code: 40R2; Tolerance_%: 1; Power_W: 0.1; VDC_V: 75; TempCo: 100 ppm/C; EIA_Code: E96; U/M: EA
R47 = CRCW06037K50FKEA: RES, 7.50k ohm, 1%, 0.1W, 0603; Manufacturer: Vishay-Dale; CompType: Resistor; Res_ohm: 7500; Value_Code: 7k50; Tolerance_%: 1; Power_W: 0.1; VDC_V: 75; TempCo: 100 ppm/C; EIA_Code: E96; U/M: EA
R50 = CRCW06033K01FKEA: RES, 3.01k ohm, 1%, 0.1W, 0603; Manufacturer: Vishay-Dale; CompType: Resistor; Res_ohm: 3010; Value_Code: 3k01; Tolerance_%: 1; Power_W: 0.1; VDC_V: 75; TempCo: 100 ppm/C; EIA_Code: E96; U/M: EA
R53 R54 R58 R59 = CRCW12060000Z0EA: RES, 0 ohm, 5%, 0.25W, 1206; Manufacturer: Vishay-Dale; CompType: Resistor; Value: 0; Value_Code: 0000; Tolerance_%: 5; Power_W: 0.25; VDC_V: 200; TempCo: 200 ppm/C; EIA_Code: E24; U/M: EA
TP1 TP3 = 5010: Test Point, Multipurpose, Red, TH; Manufacturer: Keystone; CompType: Test Point Loop; U/M: EA
TP2 TP7-TP9 = 5012: Test Point, Multipurpose, White, TH; Manufacturer: Keystone; CompType: Test Point Loop; U/M: EA
TP4 TP5 = 5011: Test Point, Multipurpose, Black, TH; Manufacturer: Keystone; CompType: Test Point Loop; U/M: EA
TP14 = 5009: Test Point, Compact, Yellow, TH; Manufacturer: Keystone; CompType: Test Point Loop; U/M: EA
U1 U2 = LM5122MH/NOPB: Wide Input Synchronous Boost Controller with Multiple Phase Capability, PWP0020A; Manufacturer: Texas Instruments; SymbolCreator: a0411947; CompType: IC; U/M: EA
U3 = LP2951CSD: Series of Adjustable Micropower Voltage Regulators, 8-pin LLP; Manufacturer: Texas Instruments; PackageTopMarking: NS*UZXYTT*2951ACB; PowerWise: N; CompType: LDO IC
U4 = LM321MF: Low Power Single Op Amp, DBV0005A; Manufacturer: Texas Instruments; CompType: OpAmp IC; SymbolCreator: a0411595

## Sheet PMP9386_Hardware_ANSI-B.SchDoc
size 431 x 279 mm; Date: Not shown in title block; ApprovedBy: Not shown in title block; CheckedBy: Not shown in title block; Author: Not shown in title block; CompanyName: Not shown in title block; Engineer: Not shown in title block; Organization: Not shown in title block; Address1: Not shown in title block; Address2: Not shown in title block; Address3: Not shown in title block; Address4: Not shown in title block; DocumentNumber: 2; Revision: Use project parameter SCH_Rev; SheetNumber: 2; SheetTotal: 2; PageSetup: Record=PageOptions|CenterHorizontal=True|CenterVertical=True|PrintScale=1.00|XCorrection=1.00|YCorrection=1.00|PrintKind=0|BorderSize=5000000|LeftOffset=0|BottomOffset=0|Orientation=2|PaperLength=1000|PaperWidth=1000|Scale=100|PaperSource=15|PrintQuality=600|MediaType=1|DitherType=10|PaperKind=Letter|PrintScaleMode=1
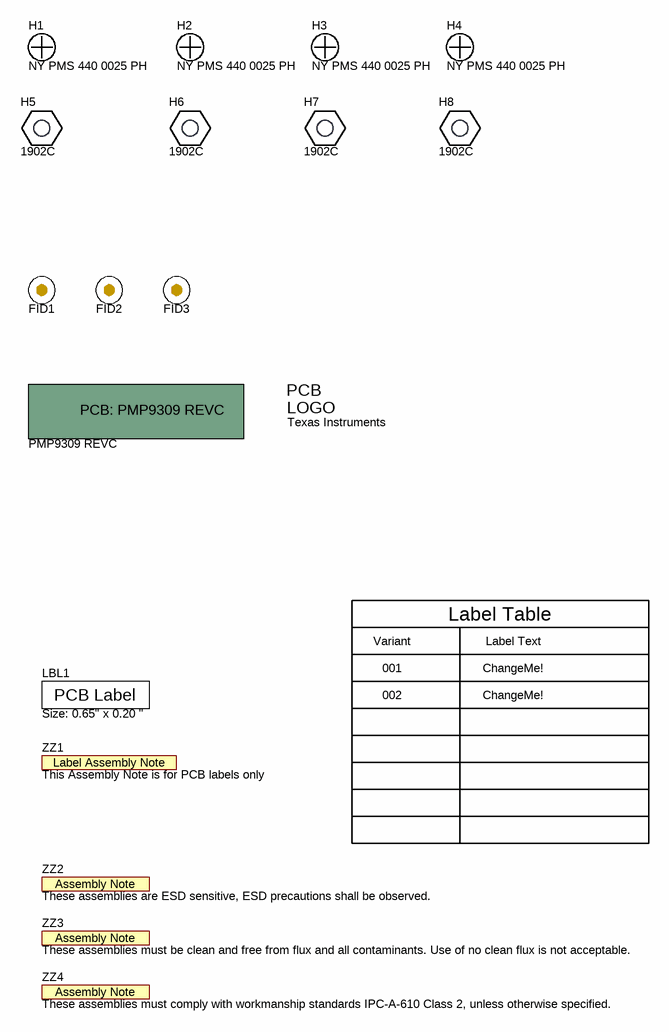
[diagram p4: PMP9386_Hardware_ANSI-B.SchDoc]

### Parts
!PCB  PMP9309 REVC  (mechanical)
FID1  Fiducial  [Fiducial10-20]  (value not drawn)
FID2  Fiducial  [Fiducial10-20]  (value not drawn)
FID3  Fiducial  [Fiducial10-20]  (value not drawn)
H1  NY PMS 440 0025 PH  [NY PMS 440 0025 PH]
H2  NY PMS 440 0025 PH  [NY PMS 440 0025 PH]
H3  NY PMS 440 0025 PH  [NY PMS 440 0025 PH]
H4  NY PMS 440 0025 PH  [NY PMS 440 0025 PH]
H5  1902C  [Keystone_1902C]
H6  1902C  [Keystone_1902C]
H7  1902C  [Keystone_1902C]
H8  1902C  [Keystone_1902C]
LBL1  Size: 0.65" x 0.20 "  [Label_650x200]
Logo1  Texas Instruments  [TI_Stacked_SolderMask_Small]  (no BOM)
ZZ1  This Assembly Note is for PCB labels only  [AssemblyNoteLabel]  (no BOM)
ZZ2  These assemblies are ESD sensitive, ESD precautions shall be observed.  [AssemblyNote]  (no BOM)
ZZ3  These assemblies must be clean and free from flux and all contaminants. Use of no clean flux is not acceptable.  [AssemblyNote]  (no BOM)
ZZ4  These assemblies must comply with workmanship standards IPC-A-610 Class 2, unless otherwise specified.  [AssemblyNote]  (no BOM)

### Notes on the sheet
- Variant
- Label Table
- Label Text
- 001
- 002
- ChangeMe!

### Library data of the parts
!PCB = PCB_OtherProject: Manufacturer: Any; SymbolCreator: a0412235; CompType: PCB; U/M: EA
FID1-FID3 = Fiducial: Fiducial mark.  There is nothing to buy or mount.; SymbolCreator: codlsc
H1-H4 = NY PMS 440 0025 PH: Machine Screw, Round, #4-40 x 1/4, Nylon, Philips panhead; Manufacturer: B&F Fastener Supply; CompType: Hardware; SymbolCreator: codlsc; U/M: EA
H5-H8 = 1902C: Standoff, Hex, 0.5"L #4-40 Nylon; Manufacturer: Keystone; CompType: Hardware
LBL1 = THT-14-423-10: Thermal Transfer Printable Labels, 0.650" W x 0.200" H - 10,000 per roll; Manufacturer: Brady; SymbolCreator: a0412235; CompType: Label
Logo1 = TI_Logo: Texas Instrument Corporate Signature; SymbolCreator: codlsc
ZZ1 = AssemblyNoteLabel: SymbolCreator: a0412235
ZZ2-ZZ4 = AssemblyNote: SymbolCreator: codlsc

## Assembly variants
001: not fitted C1 C2 C3 C4 C5 C7 C8 C9 C10 C11 C12 C13 C14 C25 C26 C27 C28 C29 C31 C32 C33 C35 C36 C37 C38 C39 C40 C41 C42 C43 C44 C50 C51 C52 D2 D4 FID1 FID2 FID3 Q2 Q4 Q5 Q6 Q8 Q9 Q11 Q14 Q15 Q16 Q17 Q18 R1 R6 R7 R17 R22 R25 R31 R32 R39 R40 R41 R42 R43 R44 R45 R46 R47 R48 R49 R50 R53 R54 R55 R58 R59 TP14 U3 U4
